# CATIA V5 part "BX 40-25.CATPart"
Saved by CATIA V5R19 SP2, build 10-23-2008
Part number: BX 40-25
Bounding box of the stored display mesh (mm): x -12.497 to 12.497, y -12.358 to 12.358, z 0 to 120
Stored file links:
  C:\Users\Bora\Desktop\3D Katı model\BX serisi\BX 40\BX 40-10\BX 40-25.CATPart
  C:\Program Files\Dassault Systemes\B19\intel_a\reffiles\standard\MetricThickPitch.txt
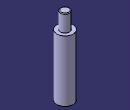
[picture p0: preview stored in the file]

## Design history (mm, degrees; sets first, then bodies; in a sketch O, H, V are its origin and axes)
Body1 (main body)
  Sketch1 on yz-plane, origin (0, 0, 0), H (0, 1, 0), V (0, 0, 1)
    point P1 (7, 119)
    point P3 (7, 119)
    arc A1 centre (6, 119) radius 1 from (7, 119) to (6, 120) ccw
    line L1 (7, 119) -> (7, 94)
    line L2 (12.5, 94) -> (12.5, 0)
    line L3 (6, 120) -> (0, 120)
    point P7 (0, 120)
    line L4 (12.5, 94) -> (7, 94)
    line L5 (12.5, 0) -> (0, 0)
    tangency: L3 A1
    coincidence: P7 V, P1 P3
    horizontal: L4 H, L5 H
  Shaft1: profile Sketch1, axis Sketch1.V, angle 360
  Sketch2 on face of Shaft1 from Sketch1.L5, origin (0, 0, 0), H (1, 0, 0), V (0, -1, 0)
    point P1 (6, 0)
    distance P1 V = 6
  Hole1: placed by Sketch2, at (6, 0, 0) direction (0, 0, 1), diameter 3.242, depth 5, threaded "M4", thread diameter 4, thread depth 5, pitch 0.7
  Sketch3 on face of Shaft1 from Sketch1.L5, origin (0, 0, 0), H (1, 0, 0), V (0, -1, 0)
    point P1 (-6, 0)
    distance P1 V = 6
    distance P1 H = 0
  Hole2: placed by Sketch3, at (-6, 0, 0) direction (0, 0, 1), diameter 3.242, depth 5, threaded "M4", thread diameter 4, thread depth 5, pitch 0.7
